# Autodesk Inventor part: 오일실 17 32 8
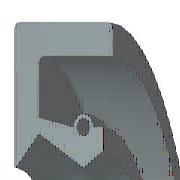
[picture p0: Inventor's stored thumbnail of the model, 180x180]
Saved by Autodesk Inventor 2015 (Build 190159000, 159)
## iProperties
IsCustomPart: 1
Created: 2012-02
Part Number: 오일실 17 32 8
Material: 고무
Description: 오일-실
Document SubType Name: Modeling
Standard: KS B 2804
Designer: mduedu
Standards Organization: KS
Language: ko-KR
Size Designation: D - 17 32 8
Categories: <MemberInstance><Categories><Category DisplayName="샤프트 부품" InternalName="7f7aeb1f-a693-4053-b835-cee3144e0d98" Mnemonic="SHFT"><Category DisplayName="실링" Intern
Density: 0.93 g/cm^3
Appearance: 고무 - 검은색 - 버전 1.1
Mass: 2.28027 g
Surface Area: 32.1224 cm^2
Volume: 2.45191 cm^3
Author: mduedu
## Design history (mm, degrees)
revolve "본체" stored, may be unused: angle "d17" = 90 deg
revolve "스프링1" stored, may be unused: angle "d18" = 90 deg
body "Solid1"
sketch "스케치1"
  geometry: L1 (0, 16)-(8, 16); L2 (8, 14.25)-(1.75, 14.25); L3 (1.75, 10.25)-(4.9, 8.5); L4 (4.9, 8.5)-(0, 8.5); L5 (0, 0)-(9.586, 0) reference; L6 (4.9, 8.5)-(6.3, 9.375); L7 (0, 18)-(0, -3) reference; L8 (-1.941, 0)-(11.507, 0) reference; L9 (4.2, 10.6)-(1.75, 11.21); L10 (1.75, 11.21)-(1.75, 14.25); L11 (0, 16)-(0, 8.588); L12 (4.9, 8.5)-(0, 8.5); L13 (1.75, 10.25)-(0.152, 8.528); L14 (8, 16)-(8, 14.25); L15 (5.6, 10.6)-(6.3, 10.6); L16 (6.3, 10.6)-(6.3, 9.375); C1 r 0.455 at (4.9, 10.6); A1 r 0.7 centre (4.9, 10.6) between (5.6, 10.6) and (4.2, 10.6); A2 r 0.088 centre (0.088, 8.588) between (0, 8.588) and (0.152, 8.528); 1 further point
  constraints: 28 end point, 5 horizontal alignment, 5 point on line, 4 point on circle, 4 vertical alignment, 3 centre point, 3 tangent, 2 collinear, 2 horizontal, 2 perpendicular, 1 coincident, 1 parallel
  dimensions: "d0" = 32 diameter of L1 L5 (= SD2); "d1" = 1.75 distance of L1.end L2.start (= SD); "d2" = 0.91 diameter of C1 (= SPDI); "d3" = 1.4 diameter of A1 (= SPDA); "d4" = 17 diameter of L3.end L5 (= NND); "d5" = 20.5 diameter of L3.start L5 (= TKDM); "d7" = 22.42 diameter of L9.end L5 (= TKDM + 0.24 x SWDT); "d8" = 1.75 distance between parallel lines of L11 L10 (= SD); "d9" = 4.9 distance from line of L11 C1.centre (= SPDST); "d10" = 21.2 diameter of C1.centre L5 (= HLDM); "d11" = 0.0875 radius of A2 (= 0.25 x LAB); "d12" = 6.3 distance between parallel lines of L11 L16 (= SDI); "d13" = 18.75 diameter of L6.end L5 (= ABDM); "d14" = 8 distance from line of L11 L1.end (= SWDT)
fillet "모깎기1" dims "d6" = 0.3 (= RR)
other parameters: "SD2" = 32 [user parameter; used in 1 equation term], "SWDT" = 8 [user parameter; used in 2 equation terms], "RR" = 0.3 [user parameter; used in 1 equation term], "SD" = 1.75 [user parameter; used in 2 equation terms], "NND" = 17 [user parameter; used in 1 equation term], "SPDA" = 1.4 [user parameter; used in 1 equation term], "SPDI" = 0.91 [user parameter; used in 1 equation term], "TKDM" = 20.5 [user parameter; used in 2 equation terms], "HLDM" = 21.2 [user parameter; used in 1 equation term], "ABDM" = 18.75 [user parameter; used in 1 equation term], "SDI" = 6.3 [user parameter; used in 1 equation term], "SPDST" = 4.9 [user parameter; used in 1 equation term], "LAB" = 0.35 [user parameter; used in 1 equation term], "d15" = 0, "d16" = 0, "d19" = 0
